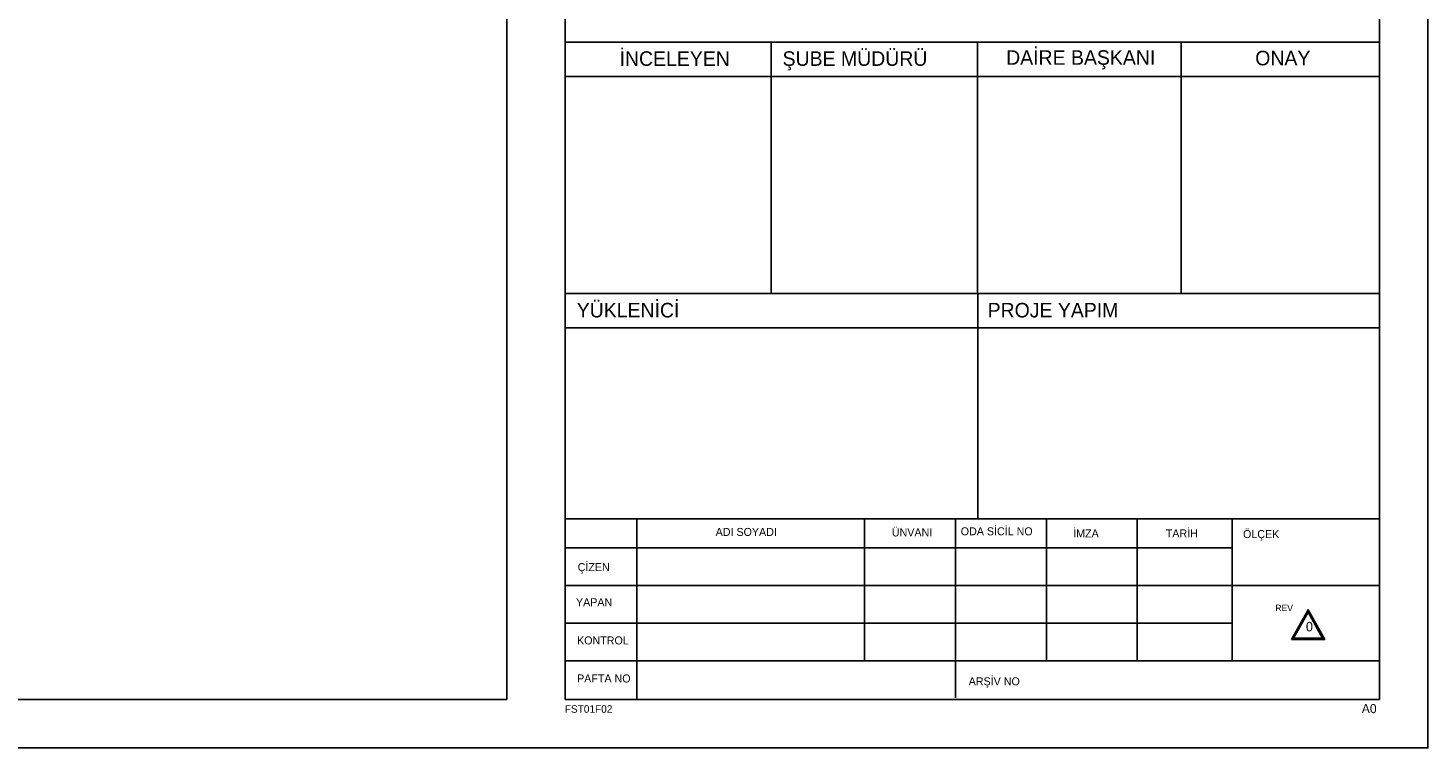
# Model space of a CAD drawing. Extents: x -10 to 1145, y -10 to 821.
# Drawn here: x 856.2 to 1145, y -10 to 138.4 of the extents above; entities that cross this region are included whole.
import ezdxf

# ---------------------------------------------------------------- set-up
doc = ezdxf.new("R2010")
doc.units = 0
for name, color, linetype in [('Level 20', 7, 'Continuous'), ('Level 50', 7, 'Continuous'), ('Level 51', 7, 'Continuous'), ('Level 6', 7, 'Continuous'), ('Level 7', 7, 'Continuous')]:
    doc.layers.add(name, color=color, linetype=linetype)

msp = doc.modelspace()

# ---------------------------------------------------------------- linework, layer by layer
at = {"layer": 'Level 20'}
msp.add_line((1052.15, 37.22), (1052.15, 83.68), dxfattribs=at)
at = {"layer": 'Level 50'}
msp.add_lwpolyline([(0, 0), (955, 0), (955, 811), (0, 811)], close=True, dxfattribs=at)
at = {"layer": 'Level 51'}
msp.add_lwpolyline([(-10, -10), (1145, -10), (1145, 821), (-10, 821)], close=True, dxfattribs=at)
at = {"layer": 'Level 6'}
for p, q in [((967.03, 0), (967.03, 262.93)), ((1135, 0), (1135, 262.93)), ((1135, 0), (1135, 262.93)), ((1135, 0), (1135, 262.93)), ((1135, 0), (1135, 262.93)), ((967.03, 135.51), (1135, 135.51)), ((1009.56, 83.68), (1009.56, 135.51)), ((1052.08, 83.68), (1052.08, 135.51)), ((1094.09, 83.68), (1094.09, 135.51)), ((967.03, 128.43), (1135, 128.43)), ((967.03, 128.43), (1135, 128.43)), ((967.03, 128.43), (1135, 128.43)), ((967.03, 83.68), (1135, 83.68)), ((967.03, 83.68), (1135, 83.68)), ((967.03, 83.68), (1135, 83.68)), ((967.03, 83.68), (1135, 83.68)), ((967.03, 83.68), (1135, 83.68)), ((967.03, 76.65), (1135, 76.65)), ((967.03, 37.27), (1135, 37.27)), ((967.03, 37.27), (1135, 37.27)), ((967.03, 37.27), (1135, 37.27)), ((967.03, 37.27), (1135, 37.27)), ((981.8, 0), (981.8, 37.13)), ((1028.79, 7.98), (1028.79, 37.27)), ((1047.54, 0.32), (1047.54, 37.27)), ((1066.29, 8.15), (1066.29, 37.27)), ((1085.04, 8.15), (1085.04, 37.27)), ((1104.62, 37.27), (1104.62, 7.98)), ((967.03, 31.27), (1104.38, 31.27)), ((967.03, 31.27), (1076.74, 31.27)), ((967.03, 31.27), (1076.74, 31.27)), ((967.03, 31.27), (1076.74, 31.27)), ((966.89, 23.52), (1134.87, 23.52)), ((967.03, 15.73), (1104.62, 15.73)), ((967.03, 7.98), (1134.87, 7.98)), ((967.03, 0), (1135, 0)), ((967.03, 0), (1135, 0)), ((967.03, 0), (1135, 0)), ((967.03, 0), (1135, 0)), ((967.03, 0), (1135, 0)), ((967.03, 0), (1135, 0)), ((967.03, 0), (1135, 0)), ((967.03, 0), (1135, 0))]:
    msp.add_line(p, q, dxfattribs=at)
at = {"layer": 'Level 7'}
for points in [[(1116.85, 12.39), (1120.27, 18.51), (1123.69, 12.39)], [(1116.85, 12.39), (1120.27, 18.51), (1123.69, 12.39)], [(1116.85, 12.39), (1120.27, 18.51), (1123.69, 12.39)], [(1116.85, 12.39), (1120.27, 18.51), (1123.69, 12.39)], [(1117.28, 12.64), (1120.27, 18.01), (1123.27, 12.64)], [(1117.28, 12.64), (1120.27, 18.01), (1123.27, 12.64)], [(1117.28, 12.64), (1120.27, 18.01), (1123.27, 12.64)], [(1117.28, 12.64), (1120.27, 18.01), (1123.27, 12.64)]]:
    msp.add_lwpolyline(points, close=True, dxfattribs=at)

# ---------------------------------------------------------------- texts
for s, height, p in [('İNCELEYEN', 3, (978.26, 130.64)), ('ŞUBE MÜDÜRÜ', 3, (1011.88, 130.64)), ('DAİRE BAŞKANI', 3, (1057.99, 130.86)), ('ONAY', 3, (1109.37, 130.75)), ('YÜKLENİCİ', 3, (969.43, 78.77)), ('PROJE YAPIM', 3, (1054.17, 78.77)), ('ADI SOYADI', 1.65, (998.08, 33.72)), ('ÜNVANI', 1.65, (1034.42, 33.62)), ('ODA SİCİL NO', 1.65, (1048.63, 33.85)), ('İMZA', 1.65, (1071.82, 33.41)), ('TARİH', 1.65, (1090.92, 33.41)), ('ÖLÇEK', 1.65, (1106.85, 33.28)), ('ÇİZEN', 1.65, (969.62, 26.47)), ('YAPAN', 1.65, (969.27, 19.23)), ('REV', 1.32, (1113.52, 18.21)), ('0', 1.95, (1119.82, 14.05)), ('KONTROL', 1.65, (969.49, 11.35)), ('PAFTA NO', 1.65, (969.5, 3.51)), ('ARŞİV NO', 1.65, (1050.27, 2.92)), ('FST01F02', 1.555, (966.96, -2.74)), ('A0', 1.866, (1131.35, -2.81))]:
    msp.add_text(s, height=height, dxfattribs=at).set_placement(p)

doc.saveas('drawing.dxf')
